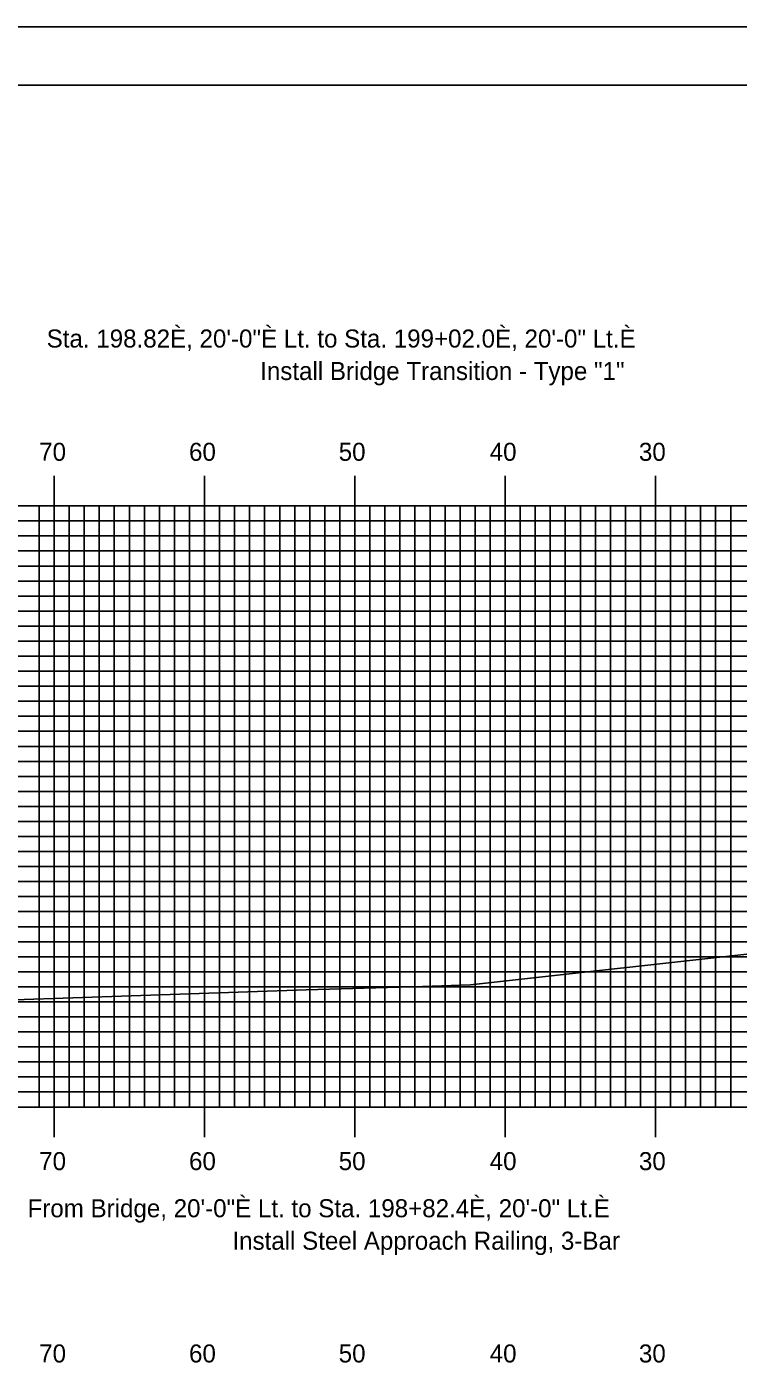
# Model space of a CAD drawing. Extents: x 1790124 to 1790467, y 442591 to 442811.
# Drawn here: x 1790217.9 to 1790265.2, y 442721.4 to 442810.5 of the extents above; entities that cross this region are included whole.
import ezdxf

# ---------------------------------------------------------------- set-up
doc = ezdxf.new("R2010")
doc.units = 0
for name, color, linetype in [('ANNOTATION', 7, 'Continuous'), ('BORDER', 7, 'Continuous'), ('H_V ANNOTATION', 7, 'Continuous'), ('MAJOR', 7, 'Continuous'), ('MINOR', 7, 'Continuous'), ('PLOT BOUNDARY', 7, 'Continuous'), ('S_Roadway_Centerline', 7, 'Continuous')]:
    doc.layers.add(name, color=color, linetype=linetype)

msp = doc.modelspace()

# ---------------------------------------------------------------- linework, layer by layer
at = {"layer": 'BORDER'}
msp.add_lwpolyline([(1790140.096, 442596.665), (1790460.096, 442596.665), (1790460.096, 442806.665), (1790140.096, 442806.665)], close=True, dxfattribs=at)
at = {"layer": 'MAJOR'}
for p, q in [((1790219.696, 442780.669), (1790219.696, 442778.665)), ((1790229.696, 442780.669), (1790229.696, 442778.665)), ((1790239.696, 442780.669), (1790239.696, 442778.665)), ((1790249.696, 442780.669), (1790249.696, 442778.665)), ((1790259.696, 442780.669), (1790259.696, 442778.665)), ((1790149.696, 442778.665), (1790429.696, 442778.665)), ((1790149.696, 442778.665), (1790429.696, 442778.665)), ((1790219.696, 442738.665), (1790219.696, 442778.665)), ((1790229.696, 442738.665), (1790229.696, 442778.665)), ((1790239.696, 442738.665), (1790239.696, 442778.665)), ((1790249.696, 442738.665), (1790249.696, 442778.665)), ((1790259.696, 442738.665), (1790259.696, 442778.665)), ((1790149.696, 442773.665), (1790429.696, 442773.665)), ((1790149.696, 442768.665), (1790429.696, 442768.665)), ((1790149.696, 442763.665), (1790429.696, 442763.665)), ((1790149.696, 442758.665), (1790429.696, 442758.665)), ((1790149.696, 442753.665), (1790429.696, 442753.665)), ((1790149.696, 442748.665), (1790429.696, 442748.665)), ((1790149.696, 442743.665), (1790429.696, 442743.665)), ((1790149.696, 442738.665), (1790429.696, 442738.665)), ((1790149.696, 442738.665), (1790429.696, 442738.665)), ((1790219.696, 442736.661), (1790219.696, 442738.665)), ((1790229.696, 442736.661), (1790229.696, 442738.665)), ((1790239.696, 442736.661), (1790239.696, 442738.665)), ((1790249.696, 442736.661), (1790249.696, 442738.665)), ((1790259.696, 442736.661), (1790259.696, 442738.665))]:
    msp.add_line(p, q, dxfattribs=at)
at = {"layer": 'MINOR'}
for p, q in [((1790218.696, 442738.665), (1790218.696, 442778.665)), ((1790220.696, 442738.665), (1790220.696, 442778.665)), ((1790221.696, 442738.665), (1790221.696, 442778.665)), ((1790222.696, 442738.665), (1790222.696, 442778.665)), ((1790223.696, 442738.665), (1790223.696, 442778.665)), ((1790224.696, 442738.665), (1790224.696, 442778.665)), ((1790225.696, 442738.665), (1790225.696, 442778.665)), ((1790226.696, 442738.665), (1790226.696, 442778.665)), ((1790227.696, 442738.665), (1790227.696, 442778.665)), ((1790228.696, 442738.665), (1790228.696, 442778.665)), ((1790230.696, 442738.665), (1790230.696, 442778.665)), ((1790231.696, 442738.665), (1790231.696, 442778.665)), ((1790232.696, 442738.665), (1790232.696, 442778.665)), ((1790233.696, 442738.665), (1790233.696, 442778.665)), ((1790234.696, 442738.665), (1790234.696, 442778.665)), ((1790235.696, 442738.665), (1790235.696, 442778.665)), ((1790236.696, 442738.665), (1790236.696, 442778.665)), ((1790237.696, 442738.665), (1790237.696, 442778.665)), ((1790238.696, 442738.665), (1790238.696, 442778.665)), ((1790240.696, 442738.665), (1790240.696, 442778.665)), ((1790241.696, 442738.665), (1790241.696, 442778.665)), ((1790242.696, 442738.665), (1790242.696, 442778.665)), ((1790243.696, 442738.665), (1790243.696, 442778.665)), ((1790244.696, 442738.665), (1790244.696, 442778.665)), ((1790245.696, 442738.665), (1790245.696, 442778.665)), ((1790246.696, 442738.665), (1790246.696, 442778.665)), ((1790247.696, 442738.665), (1790247.696, 442778.665)), ((1790248.696, 442738.665), (1790248.696, 442778.665)), ((1790250.696, 442738.665), (1790250.696, 442778.665)), ((1790251.696, 442738.665), (1790251.696, 442778.665)), ((1790252.696, 442738.665), (1790252.696, 442778.665)), ((1790253.696, 442738.665), (1790253.696, 442778.665)), ((1790254.696, 442738.665), (1790254.696, 442778.665)), ((1790255.696, 442738.665), (1790255.696, 442778.665)), ((1790256.696, 442738.665), (1790256.696, 442778.665)), ((1790257.696, 442738.665), (1790257.696, 442778.665)), ((1790258.696, 442738.665), (1790258.696, 442778.665)), ((1790260.696, 442738.665), (1790260.696, 442778.665)), ((1790261.696, 442738.665), (1790261.696, 442778.665)), ((1790262.696, 442738.665), (1790262.696, 442778.665)), ((1790263.696, 442738.665), (1790263.696, 442778.665)), ((1790264.696, 442738.665), (1790264.696, 442778.665)), ((1790149.696, 442777.665), (1790429.696, 442777.665)), ((1790149.696, 442776.665), (1790429.696, 442776.665)), ((1790149.696, 442775.665), (1790429.696, 442775.665)), ((1790149.696, 442774.665), (1790429.696, 442774.665)), ((1790149.696, 442772.665), (1790429.696, 442772.665)), ((1790149.696, 442771.665), (1790429.696, 442771.665)), ((1790149.696, 442770.665), (1790429.696, 442770.665)), ((1790149.696, 442769.665), (1790429.696, 442769.665)), ((1790149.696, 442767.665), (1790429.696, 442767.665)), ((1790149.696, 442766.665), (1790429.696, 442766.665)), ((1790149.696, 442765.665), (1790429.696, 442765.665)), ((1790149.696, 442764.665), (1790429.696, 442764.665)), ((1790149.696, 442762.665), (1790429.696, 442762.665)), ((1790149.696, 442761.665), (1790429.696, 442761.665)), ((1790149.696, 442760.665), (1790429.696, 442760.665)), ((1790149.696, 442759.665), (1790429.696, 442759.665)), ((1790149.696, 442757.665), (1790429.696, 442757.665)), ((1790149.696, 442756.665), (1790429.696, 442756.665)), ((1790149.696, 442755.665), (1790429.696, 442755.665)), ((1790149.696, 442754.665), (1790429.696, 442754.665)), ((1790149.696, 442752.665), (1790429.696, 442752.665)), ((1790149.696, 442751.665), (1790429.696, 442751.665)), ((1790149.696, 442750.665), (1790429.696, 442750.665)), ((1790149.696, 442749.665), (1790429.696, 442749.665)), ((1790149.696, 442747.665), (1790429.696, 442747.665)), ((1790149.696, 442746.665), (1790429.696, 442746.665)), ((1790149.696, 442745.665), (1790429.696, 442745.665)), ((1790149.696, 442744.665), (1790429.696, 442744.665)), ((1790149.696, 442742.665), (1790429.696, 442742.665)), ((1790149.696, 442741.665), (1790429.696, 442741.665)), ((1790149.696, 442740.665), (1790429.696, 442740.665)), ((1790149.696, 442739.665), (1790429.696, 442739.665))]:
    msp.add_line(p, q, dxfattribs=at)
at = {"layer": 'PLOT BOUNDARY'}
msp.add_lwpolyline([(1790123.909, 442590.547), (1790463.909, 442590.547), (1790463.909, 442810.547), (1790123.909, 442810.547)], close=True, dxfattribs=at)
at = {"layer": 'S_Roadway_Centerline'}
msp.add_lwpolyline([(1790213.163, 442745.664), (1790236.464, 442746.473), (1790244.189, 442746.678), (1790247.389, 442746.795), (1790267.566, 442749.035), (1790270.01, 442749.367), (1790276.184, 442749.659), (1790283.128, 442749.749), (1790283.372, 442749.743), (1790288.407, 442749.935), (1790288.537, 442749.877), (1790290.284, 442750.101), (1790290.729, 442750.129), (1790290.73, 442750.131), (1790298.722, 442751.129), (1790301.756, 442751.596), (1790301.833, 442751.599), (1790304.492, 442751.852), (1790306.591, 442751.991), (1790309.21, 442752.099), (1790313.351, 442752.288)], dxfattribs=at)

# ---------------------------------------------------------------- texts
at = {"layer": 'ANNOTATION'}
for s, p in [('Sta. 198.82È, 20\'-0"È Lt. to Sta. 199+02.0È, 20\'-0" Lt.È', (1790219.197, 442789.204)), ('Install Bridge Transition - Type "1"', (1790233.4, 442787.044)), ('From Bridge, 20\'-0"È Lt. to Sta. 198+82.4È, 20\'-0" Lt.È', (1790217.926, 442731.329)), ('Install Steel Approach Railing, 3-Bar', (1790231.553, 442729.169))]:
    msp.add_text(s, height=1.2, dxfattribs=at).set_placement(p)
at = {"layer": 'H_V ANNOTATION'}
for s, p in [('70', (1790218.7, 442781.665)), ('60', (1790228.668, 442781.665)), ('50', (1790238.625, 442781.665)), ('40', (1790248.668, 442781.665)), ('30', (1790258.593, 442781.665)), ('70', (1790218.7, 442734.465)), ('60', (1790228.668, 442734.465)), ('50', (1790238.625, 442734.465)), ('40', (1790248.668, 442734.465)), ('30', (1790258.593, 442734.465)), ('70', (1790218.7, 442721.665)), ('60', (1790228.668, 442721.665)), ('50', (1790238.625, 442721.665)), ('40', (1790248.668, 442721.665)), ('30', (1790258.593, 442721.665))]:
    msp.add_text(s, height=1.2, dxfattribs=at).set_placement(p)

doc.saveas('drawing.dxf')
